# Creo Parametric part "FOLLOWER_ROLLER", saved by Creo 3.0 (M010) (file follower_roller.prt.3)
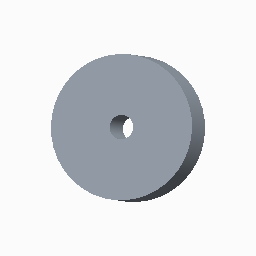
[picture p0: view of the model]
Units: millimeter Kilogram Sec (mmKs); MM, KILOGRAM, SECS

Created from: SOLID_PART_MMKS.PRT

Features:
  1. coordinate system
  2. datum plane "RIGHT"
  3. datum plane "TOP"
  4. datum plane "FRONT"
  5. sketch "Sketch 1"
  6. extrusion "Extrude 1"

Surfaces: 5 plane, 4 cylinder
